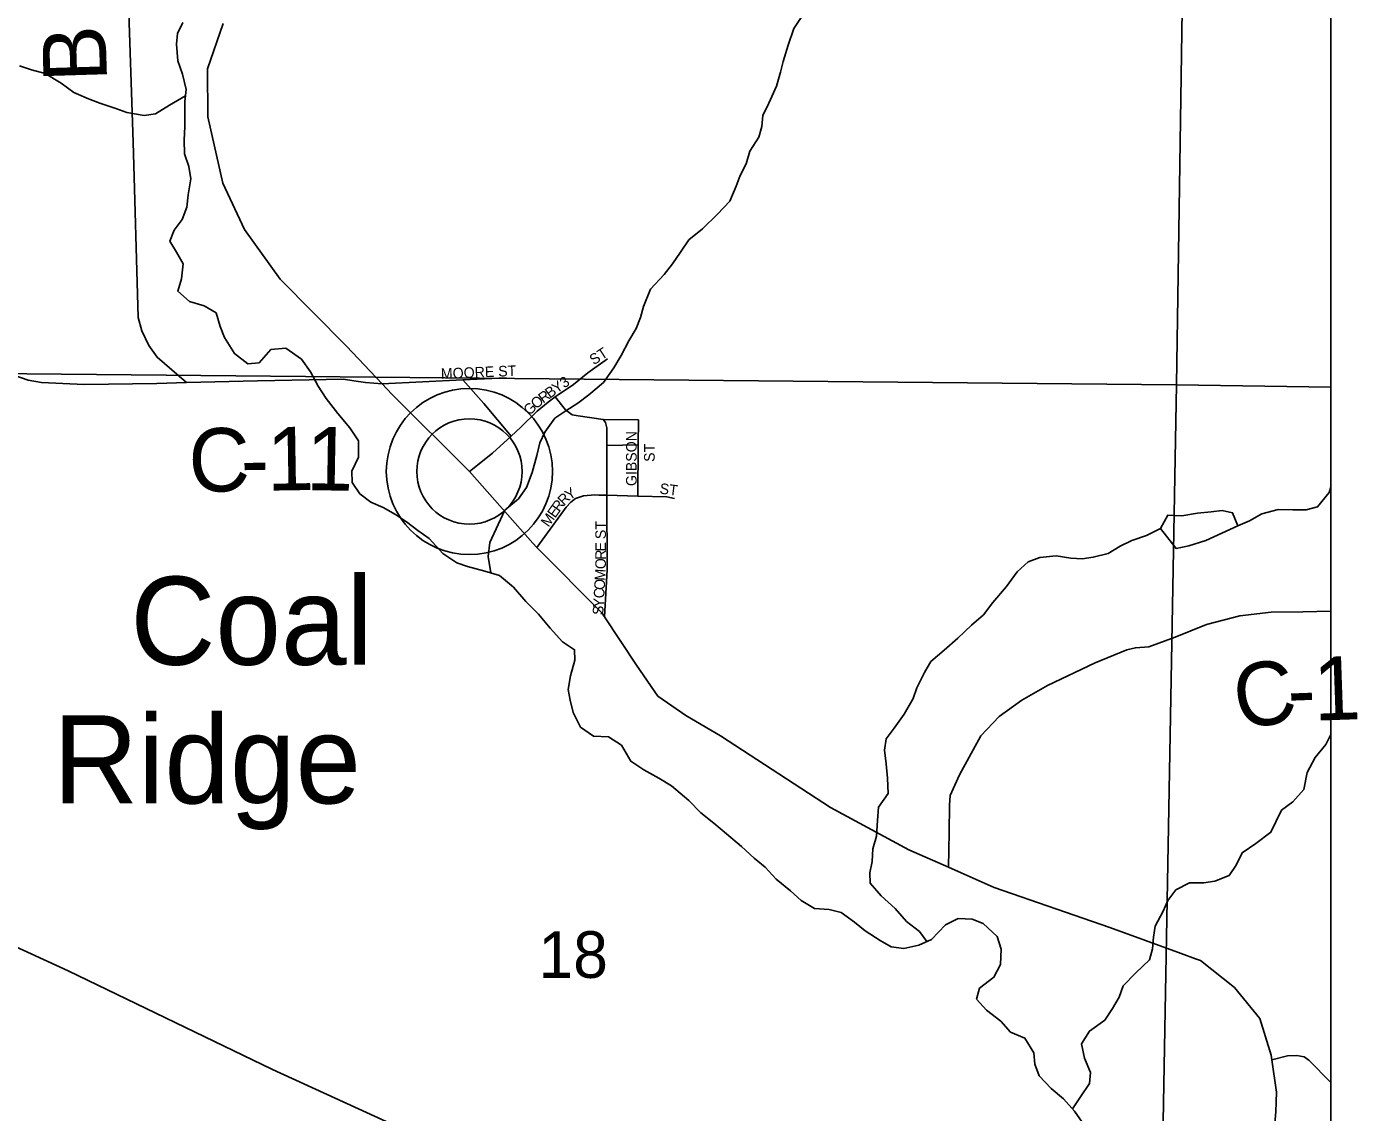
# Model space of a CAD drawing. Extents: x -452339 to 6403467, y -1 to 1814750.
# Drawn here: x -59685 to -53394, y 1553189 to 1558323 of the extents above; entities that cross this region are included whole.
import ezdxf

# ---------------------------------------------------------------- set-up
doc = ezdxf.new("R2010")
doc.units = 0
for name, color, linetype in [('GM_X_Adjacent_County', 7, 'Continuous'), ('GM_X_Adjacent_County_Text', 7, 'Continuous'), ('GM_X_County', 7, 'Continuous'), ('GM_X_County_Road', 7, 'Continuous'), ('GM_X_County_Road_Text', 7, 'Continuous'), ('GM_X_County_ROW', 7, 'Continuous'), ('GM_X_Major_Lake', 7, 'Continuous'), ('GM_X_Major_Lake_Text', 7, 'Continuous'), ('GM_X_Major_River_Text', 7, 'Continuous'), ('GM_X_Section', 7, 'Continuous'), ('GM_X_Township', 7, 'Continuous'), ('GM_X_Township_Road_Text', 7, 'Continuous'), ('GM_X_Unincorporated_Location', 7, 'Continuous')]:
    doc.layers.add(name, color=color, linetype=linetype)

msp = doc.modelspace()

# ---------------------------------------------------------------- linework, layer by layer
at = {"layer": 'GM_X_County_Road'}
for points in [[(-54160.1, 1553915.2), (-54226.4, 1553939.4), (-54564.9, 1554062.6), (-55110.6, 1554252.5), (-55267.8, 1554322.2), (-55327.9, 1554348.7), (-55514, 1554431), (-55885.4, 1554629.8), (-56405.6, 1554970.2), (-56568.2, 1555065.6), (-56700.8, 1555157.2), (-56801.6, 1555303.2), (-56954.1, 1555532.9), (-56964.8, 1555549), (-57272.9, 1555860.4), (-57292.6, 1555880.4), (-57592.1, 1556219.5), (-57959.5, 1556585.1), (-58004.9, 1556633.3), (-58173.8, 1556812.7), (-58487.5, 1557128.1), (-58654.7, 1557363.9), (-58757.8, 1557582.1), (-58829.1, 1557896.6), (-58830, 1558123.3), (-58756.7, 1558338.3)], [(-54074.7, 1551143.3), (-54513.9, 1551239.4), (-54956.8, 1551325.5), (-54974.4, 1551328.9), (-55147.6, 1551404.8), (-55304.2, 1551468.2), (-55789.9, 1551712.4), (-56093.5, 1551969.6), (-56575.7, 1552330.2), (-56923.3, 1552585.2), (-57634, 1552984.7), (-58523.1, 1553391.5), (-59488.6, 1553858), (-60265.3, 1554215.2), (-61046.1, 1554582.4), (-61573.9, 1554828.5), (-61796.9, 1554979.8), (-62272.9, 1555288.4), (-62548.2, 1555497.6), (-62897.5, 1555742.9), (-62919.8, 1555758.6), (-63040.4, 1555856.3), (-63191, 1555935.7), (-63379.6, 1556027.1)], [(-53814.9, 1552873.6), (-53808.7, 1552914.8), (-53795.4, 1553003.5), (-53780.1, 1553192.1), (-53776.5, 1553284.4), (-53798.2, 1553437.9), (-53801.2, 1553458.7), (-53856, 1553632.9), (-53974.7, 1553778.7), (-54135.5, 1553906.3), (-54160.1, 1553915.2)]]:
    msp.add_lwpolyline(points, dxfattribs=at)
at = {"layer": 'GM_X_County_Road_Text'}
for radius in [392.8, 249]:
    msp.add_circle((-57592.1, 1556219.5), radius, dxfattribs=at)
at = {"layer": 'GM_X_County_ROW'}
for points in [[(-58704.8, 1559095.9), (-58961.9, 1559007.6), (-59039.1, 1558964.1), (-59112.2, 1558908.7), (-59156.9, 1558837.7), (-59191.5, 1558754.9), (-59209.6, 1558646.4), (-59204.8, 1558484.2), (-59182.5, 1557777.2), (-59158.1, 1556948), (-59141, 1556884.2), (-59107.8, 1556814.7), (-59068.8, 1556759.3), (-58929.7, 1556639.9)], [(-53519.8, 1553330), (-53624.1, 1553435.8), (-53646.1, 1553451.8), (-53680.1, 1553457.8), (-53724, 1553455.7), (-53798.2, 1553437.9)]]:
    msp.add_lwpolyline(points, dxfattribs=at)
at = {"layer": 'GM_X_Major_River_Text'}
for points in [[(-53959.5, 1555962.5), (-53983.7, 1556024.4), (-54033.7, 1556034.3), (-54085.7, 1556028.1), (-54149.6, 1556021.9), (-54223.5, 1556009.6), (-54289.5, 1556013.4), (-54325.3, 1555949.2)], [(-54325.3, 1555949.2), (-54251.1, 1555855.3), (-54191.1, 1555867.5), (-54111.2, 1555893.8), (-53959.5, 1555962.5)]]:
    msp.add_lwpolyline(points, dxfattribs=at)
at = {"layer": 'GM_X_Section'}
for points in [[(-58004.9, 1556633.3), (-58083.7, 1556641), (-58137.8, 1556648.1), (-58188, 1556655.2), (-58593.9, 1556647.9), (-58929.7, 1556639.9), (-59069.7, 1556635.4), (-59413.6, 1556631.2), (-59615.8, 1556639.6), (-59677.9, 1556650.5), (-59746.4, 1556675.3)], [(-55327.9, 1554348.7), (-55324.5, 1554512.9), (-55322.6, 1554641.1), (-55318.6, 1554687.2), (-55274.8, 1554785.4), (-55174.9, 1554969.9), (-55087, 1555060.1), (-54981.2, 1555138.4), (-54859.3, 1555206.7), (-54633.4, 1555315.2), (-54483.5, 1555375.6), (-54443.5, 1555385.6), (-54379.6, 1555389.7), (-54255.7, 1555436), (-54107.8, 1555496.3), (-53949.8, 1555536.6), (-53801.9, 1555554.9), (-53651.9, 1555555.1), (-53519.8, 1555558.3)]]:
    msp.add_lwpolyline(points, dxfattribs=at)
at = {"layer": 'GM_X_Township'}
for points in [[(-57592.1, 1556219.5), (-57482.3, 1556305.3), (-57394, 1556387.1), (-57349.2, 1556428.6), (-57271.7, 1556505.3), (-57220, 1556547.8), (-57186.3, 1556572.2), (-57172.3, 1556582.2), (-57100.6, 1556630.9), (-57033, 1556685.5), (-56939.5, 1556752.4)], [(-58004.9, 1556633.3), (-57622.7, 1556652.3), (-57418.9, 1556662.4)], [(-57622.7, 1556652.3), (-57524.1, 1556541.4), (-57394, 1556387.1)], [(-56954.1, 1555532.9), (-56940.1, 1555754.5), (-56941.7, 1556107.2), (-56942.7, 1556342.4), (-56943.1, 1556425.7), (-56949.3, 1556451.7), (-56959.4, 1556465.7), (-57077.5, 1556482.8), (-57105.6, 1556486.6), (-57137.7, 1556510.4), (-57186.3, 1556572.2)], [(-56796.6, 1556103.2), (-56794.4, 1556346), (-56793.3, 1556463), (-56959.4, 1556465.7)], [(-56794.4, 1556346), (-56942.7, 1556342.4)], [(-57272.9, 1555860.4), (-57134.3, 1556051.5), (-57112.5, 1556073.8), (-57090.6, 1556092), (-57052.7, 1556104.3), (-56998.7, 1556108.7), (-56979.5, 1556108.2)], [(-56979.5, 1556108.2), (-56978.4, 1556108.2), (-56941.7, 1556107.2), (-56796.6, 1556103.2), (-56658.6, 1556099.4), (-56622.5, 1556091.6)]]:
    msp.add_lwpolyline(points, dxfattribs=at)
at = {"layer": 'GM_X_Township_Road_Text'}
for points in [[(-57835.9, 1555940.9), (-57890, 1555980.8), (-57942.1, 1556016.6), (-58000.2, 1556048.5), (-58058.3, 1556074.3), (-58110.4, 1556114.2), (-58146.5, 1556168.1), (-58148.7, 1556220.2), (-58116.9, 1556286.4), (-58117.1, 1556364.5), (-58157.3, 1556426.4), (-58213.5, 1556494.3), (-58269.7, 1556564.2), (-58307.8, 1556622.1), (-58344, 1556690.1), (-58386.2, 1556750), (-58460.3, 1556801.8), (-58530.3, 1556795.6), (-58586.1, 1556733.3), (-58640, 1556729.1), (-58702.2, 1556776.9), (-58750.4, 1556852.9), (-58770.5, 1556904.9), (-58788.7, 1556968.9), (-58846.8, 1557002.7), (-58914.8, 1557022.5), (-58971, 1557072.4), (-58953.1, 1557130.5), (-58945.4, 1557200.6), (-58977.5, 1557256.6), (-59007.7, 1557308.6), (-58987.8, 1557360.7), (-58950, 1557410.9), (-58928.2, 1557469), (-58922.4, 1557527.1), (-58908.6, 1557603.3), (-58918.8, 1557661.3), (-58939, 1557721.3), (-58941.2, 1557785.4), (-58937.4, 1557851.5), (-58937.6, 1557919.6), (-58937.7, 1557969.7), (-58931.9, 1558025.8), (-58948.1, 1558097.8), (-58970.3, 1558161.8), (-58976.5, 1558239.9), (-58972.7, 1558290), (-58946.9, 1558342.1)], [(-57490.9, 1555739.7), (-57503.7, 1555817.9), (-57495.9, 1555884), (-57456.2, 1555968.3), (-57424.4, 1556036.5), (-57360.6, 1556090.8), (-57322.7, 1556143), (-57295, 1556215.1), (-57273.2, 1556295.3), (-57259.4, 1556355.4), (-57235.6, 1556405.6), (-57187.8, 1556471.8), (-57135.9, 1556506.1), (-57080.1, 1556542.3), (-57028.2, 1556582.5), (-56958.4, 1556640.9), (-56908.7, 1556709.1), (-56874.8, 1556767.3), (-56839.1, 1556837.5), (-56803.3, 1556895.7), (-56783.4, 1556947.9), (-56769.6, 1557000), (-56735.9, 1557082.2), (-56672.1, 1557150.5), (-56632.3, 1557200.7), (-56594.5, 1557256.9), (-56554.7, 1557315.1), (-56490.8, 1557367.4), (-56419.1, 1557435.7), (-56361.3, 1557498), (-56331.5, 1557568.2), (-56311.7, 1557618.3), (-56283.9, 1557674.5), (-56266.1, 1557734.6), (-56224.3, 1557800.9), (-56210.4, 1557851), (-56204.6, 1557903.1), (-56176.8, 1557961.3), (-56141, 1558041.5), (-56121.3, 1558107.6), (-56109.4, 1558157.7), (-56085.7, 1558235.9), (-56057.9, 1558314.1), (-56018.1, 1558376.3)], [(-58935, 1557995.4), (-59009.6, 1557951.4), (-59075.5, 1557911.1), (-59129.4, 1557902.9), (-59211.4, 1557916.7), (-59263.5, 1557936.5), (-59339.5, 1557960.3), (-59393.6, 1557982.1), (-59461.6, 1558011.9), (-59521.8, 1558055.8), (-59597.9, 1558101.6), (-59661.9, 1558119.4), (-59719.9, 1558137.2)], [(-55429.8, 1553996.3), (-55465, 1554044.9), (-55525.2, 1554090.8), (-55579.3, 1554152.7), (-55645.5, 1554212.5), (-55697.6, 1554272.4), (-55699.8, 1554322.4), (-55688, 1554374.5), (-55684.1, 1554434.6), (-55668.3, 1554494.7), (-55662.6, 1554568.9), (-55658.8, 1554632.9), (-55613, 1554697.2), (-55615.2, 1554769.3), (-55621.4, 1554837.3), (-55629.6, 1554901.4), (-55621.8, 1554955.5), (-55583.9, 1555005.6), (-55536.2, 1555071.9), (-55494.4, 1555146.1), (-55476.6, 1555196.3), (-55440.8, 1555268.5), (-55411, 1555320.6), (-55347.2, 1555374.9), (-55283.4, 1555431.2), (-55217.6, 1555493.5), (-55161.7, 1555541.8), (-55117.9, 1555600), (-55052.2, 1555676.3), (-55002.4, 1555744.6), (-54950.6, 1555792.8), (-54894.7, 1555813), (-54818.7, 1555821.3), (-54748.7, 1555809.5), (-54694.7, 1555805.7), (-54642.8, 1555813.9), (-54572.9, 1555832.2), (-54515, 1555866.4), (-54461.1, 1555892.6), (-54391.2, 1555916.9), (-54325.3, 1555949.2), (-54289.5, 1556013.4), (-54223.5, 1556009.6), (-54149.6, 1556021.9), (-54085.7, 1556028.1), (-54033.7, 1556034.3), (-53983.7, 1556024.4), (-53959.5, 1555962.5), (-53903.6, 1555986.7), (-53845.7, 1556018.9), (-53767.8, 1556039.2), (-53699.8, 1556037.4), (-53635.9, 1556037.7), (-53581.9, 1556051.9), (-53528.1, 1556120.1), (-53519.8, 1556144.7)], [(-54684.5, 1553126.6), (-54730.7, 1553194.6), (-54782.9, 1553252.4), (-54841, 1553302.3), (-54899.2, 1553362.1), (-54919.3, 1553416.1), (-54923.5, 1553470.2), (-54965.7, 1553540.1), (-55033.7, 1553567.9), (-55079.9, 1553619.8), (-55148, 1553671.6), (-55194.2, 1553723.5), (-55180.3, 1553775.6), (-55112.5, 1553827.9), (-55080.7, 1553888.1), (-55078.9, 1553960.2), (-55097.1, 1554020.2), (-55163.3, 1554082), (-55215.3, 1554101.9), (-55281.3, 1554105.6), (-55341.2, 1554075.4), (-55406.9, 1554007.1), (-55466.8, 1553978.9), (-55538.8, 1553964.6), (-55598.8, 1553972.4), (-55650.8, 1554002.2), (-55720.9, 1554048.1), (-55771, 1554087.9), (-55835.2, 1554133.8), (-55891.2, 1554147.6), (-55961.2, 1554153.3), (-56023.3, 1554191.2), (-56073.4, 1554237), (-56141.5, 1554290.9), (-56193.7, 1554348.7), (-56245.8, 1554390.6), (-56305.9, 1554446.5), (-56376.1, 1554506.3), (-56436.2, 1554556.1), (-56498.4, 1554606), (-56554.5, 1554663.9), (-56636.7, 1554733.6), (-56696.8, 1554769.5), (-56766.9, 1554809.3), (-56829, 1554849.1), (-56873.2, 1554925), (-56935.3, 1554964.9), (-57005.3, 1554968.6), (-57067.4, 1555010.5), (-57101.6, 1555080.4), (-57115.7, 1555138.4), (-57125.9, 1555188.5), (-57114.1, 1555252.6), (-57094.3, 1555326.7), (-57094.5, 1555376.8), (-57152.6, 1555414.7), (-57210.8, 1555478.5), (-57264.9, 1555544.4), (-57325.1, 1555604.3), (-57383.3, 1555672.2), (-57449.4, 1555728), (-57519.5, 1555747.8), (-57601.5, 1555769.5), (-57651.5, 1555787.4), (-57717.6, 1555831.2), (-57781.8, 1555903.1), (-57835.9, 1555940.9)], [(-54741.3, 1553206.3), (-54702.9, 1553262.7), (-54661.1, 1553324.9), (-54655.3, 1553377), (-54683.5, 1553445), (-54697.7, 1553513), (-54659.9, 1553573.2), (-54588.1, 1553625.5), (-54552.3, 1553679.7), (-54520.4, 1553733.9), (-54500.6, 1553788), (-54440.8, 1553848.3), (-54377, 1553910.6), (-54363.2, 1553962.7), (-54357.4, 1554016.8), (-54349.5, 1554068.9), (-54311.8, 1554141.1), (-54289.9, 1554191.2), (-54252.1, 1554241.4), (-54188.2, 1554273.7), (-54120.2, 1554273.9), (-54068.3, 1554282.1), (-54000.4, 1554308.3), (-53966.6, 1554358.5), (-53938.7, 1554416.7), (-53874.9, 1554461), (-53803.1, 1554513.3), (-53777.3, 1554565.4), (-53753.4, 1554617.6), (-53699.6, 1554657.8), (-53647.8, 1554716), (-53632, 1554796.2), (-53594.3, 1554866.4), (-53542.5, 1554928.6), (-53519.8, 1554976.1)]]:
    msp.add_lwpolyline(points, dxfattribs=at)
at = {"layer": 'GM_X_Unincorporated_Location'}
for points in [[(-54168.4, 1561943.8), (-54249.2, 1556628.8), (-59852, 1556682.6), (-59844.9, 1556964.8), (-59755.1, 1561995.7)], [(-53519.8, 1556617.7), (-53519.8, 1561938.6), (-54168.4, 1561943.8), (-54249.2, 1556628.8)], [(-59852, 1556682.6), (-54249.2, 1556628.8), (-54346.1, 1551317.7), (-59917, 1551387.8), (-59917, 1551575.9)], [(-53519.8, 1551307.2), (-53519.8, 1556617.7), (-54249.2, 1556628.8), (-54346.1, 1551317.7)]]:
    msp.add_lwpolyline(points, close=True, dxfattribs=at)

# ---------------------------------------------------------------- texts
at = {"layer": 'GM_X_Adjacent_County'}
for s, rotation, p in [('ST', 32.74311, (-57004.3, 1556721)), ('MOORE ST', 2.45879, (-57725.9, 1556656.4)), ('Y', 34.85413, (-57179.8, 1556586.3)), ('3', 34.95026, (-57143.6, 1556611.4)), ('O', 38.8373, (-57277.2, 1556512.3)), ('R', 36.60763, (-57243.3, 1556539.6)), ('B', 36.06844, (-57211.6, 1556563.1)), ('G', 47.08677, (-57305.7, 1556481.4)), ('GIBSON', 90, (-56801.5, 1556150.4)), ('ST', 90, (-56716.1, 1556264.8)), ('Y', 34.21136, (-57119.1, 1556081.7)), ('ST', 352.86499, (-56695.1, 1556115.2)), ('R', 54.34938, (-57166.8, 1556024.7)), ('R', 45.2232, (-57145.1, 1556055.2)), ('M', 54.47079, (-57217.9, 1555953.1)), ('E', 54.47341, (-57187.2, 1555996)), ('ST', 90, (-56946.7, 1555899.6)), ('E', 89.99561, (-56946.7, 1555841.4)), ('R', 89.99405, (-56946.7, 1555801.8)), ('M', 86.64637, (-56950.3, 1555702)), ('O', 89.4861, (-56947.1, 1555757.4)), ('O', 86.63738, (-56952.8, 1555658)), ('Y', 86.63738, (-56957.8, 1555574.6)), ('C', 86.59788, (-56955.2, 1555618.5)), ('S', 86.61108, (-56959.9, 1555539.4))]:
    msp.add_text(s, height=50, rotation=rotation, dxfattribs=at).set_placement(p)
at = {"layer": 'GM_X_Adjacent_County_Text'}
for s, p in [('Coal', (-59195.1, 1555305.4)), ('Ridge', (-59560.3, 1554649.8))]:
    msp.add_text(s, height=416.67, rotation=0.00001, dxfattribs=at).set_placement(p)
at = {"layer": 'GM_X_County'}
for s, rotation, p in [('C', 1.02261, (-58917.4, 1556122.1)), ('1', 0.92631, (-58548, 1556128.6)), ('1', 359.01637, (-58365.9, 1556131.6)), ('-', 0.9992, (-58671.1, 1556126.5)), ('C', 9.29485, (-53953.6, 1554997.5)), ('1', 1.9414, (-53597.5, 1555041)), ('-', 2.1939, (-53720.2, 1555036.3))]:
    msp.add_text(s, height=300, rotation=rotation, dxfattribs=at).set_placement(p)
at = {"layer": 'GM_X_Major_Lake'}
msp.add_text('18', height=220.83, rotation=0.00001, dxfattribs=at).set_placement((-57265.7, 1553824.8))
at = {"layer": 'GM_X_Major_Lake_Text'}
msp.add_text('B', height=300, rotation=91.74103, dxfattribs=at).set_placement((-59304.9, 1558065.1))

doc.saveas('drawing.dxf')
